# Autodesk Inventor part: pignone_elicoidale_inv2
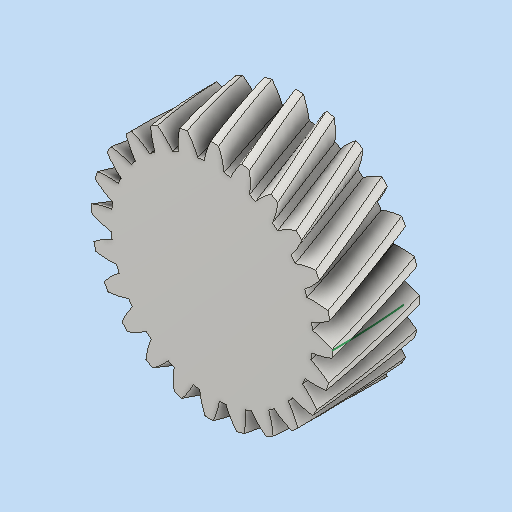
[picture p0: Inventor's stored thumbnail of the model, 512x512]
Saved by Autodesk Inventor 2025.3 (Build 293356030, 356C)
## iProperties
CustomPartVersion: 1
Created: 2025-12
Part Number: pignone_elicoidale_inv2
Material: Steel
Document SubType Name: Modeling
Designer: R5800u
Categories: <?xml version="1.0" encoding="UTF-16"?> <MemberInstance><Categories><FamilyTemplate><FamilyTemplateParameter ValueType="xs:double" Id="1" ObjectReferenceKey="da
Density: 1 g/cm^3
Appearance: Steel
Author: R5800u
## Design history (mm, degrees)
sketch "Sketch1"
  geometry: C1 r 13.77 at (0, 0)
  constraints: 1 centre point
  dimensions: "d0" = 27.54027 diameter of C1 (= da_da)
extrude "Extrusion1" new body sketch "Sketch1" distance "d1" = 10 (= da_b); taper "d2" = 0 deg
workplane "Work Plane2"
feature "Diametro primitivo" dims "d4" = 10, "d5" = 0
workplane "Work Plane8"
workplane "Work Plane9"
feature "Ingranaggio cilindrico" dims "da_b" = 10, "da_d" = 25.54027, "da_aw" = 25.54027, "da_da" = 27.54027, "da_df" = 23.04027, "da_dw" = 25.54027, angle "da_beta" = 20 deg, "da_lefttooth" = 10, "da_righttooth" = 0
sketch "Schizzo3" dims "d51" = 14
  geometry: L1 (0, 0)-(0, 7); 2 further points
  constraints: 2 coincident, 2 end point, 1 vertical, 1 vertical alignment, 2 other
hole "Foro1" sketch "Schizzo3" at (0, 7) diameter "d52" = 3.2; stored, may be unused: countersink angle "d56" = 90 deg, drill point angle "d58" = 118 deg; dims "d53" = 6, "d54" = 5.5, "d55" = 3, "d57" = 11
pattern_circular "Serie circolare1" dims angle "d60" = 360 deg
sketch "Schizzo4"
  geometry: 3 further points
  constraints: 1 other
body "Solid1"
sketch "Sketch2"
  geometry: C1 r 13.77 at (0, 0) reference; C2 r 12.77 at (0, 0)
  constraints: 1 centre point, 1 coincident
  dimensions: "d3" = 25.54027 diameter of C2 (= da_d)
body "Srf1"
other parameters: "d16" = 25.54027 (= da_aw), "d17" = 0, "d34" = 7.5 deg (computed from da_z), "d39" = 0, "d41" = 0, "d43" = 25.54027 (= da_aw), "d46" = 25.54027 (= da_aw), "d47" = 0, "d48" = 0
